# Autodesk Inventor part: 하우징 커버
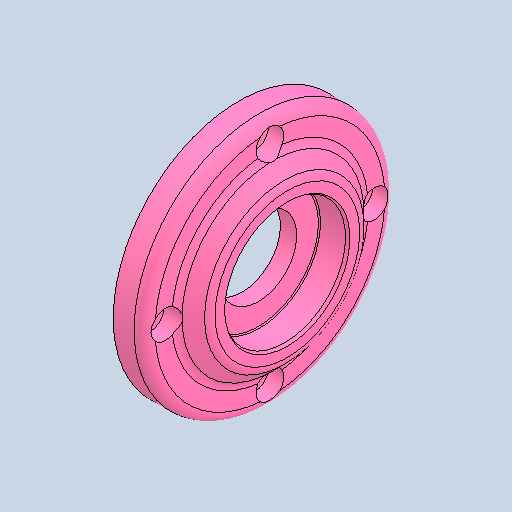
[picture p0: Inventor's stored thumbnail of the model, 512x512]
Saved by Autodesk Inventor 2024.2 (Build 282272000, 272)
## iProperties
Created: 2026-01
Part Number: 하우징 커버
Material: 알루미늄 6061
Document SubType Name: Modeling
Designer: home
Density: 2.7 g/cm^3
Appearance: 기본값
Author: jhkim
Sending System: Autodesk Inventor 2026
Preprocessor: ST-DEVELOPER v20.1
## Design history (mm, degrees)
feature "솔리드1"
node "솔리드2"
